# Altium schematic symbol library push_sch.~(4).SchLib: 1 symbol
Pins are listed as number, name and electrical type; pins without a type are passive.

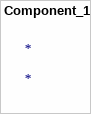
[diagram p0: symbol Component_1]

## Component_1
designator *
footprint transformer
